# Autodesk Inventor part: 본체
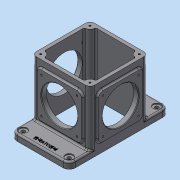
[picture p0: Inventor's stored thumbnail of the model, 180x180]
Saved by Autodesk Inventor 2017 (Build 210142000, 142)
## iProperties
Created: 2018-09
Part Number: 본체
Material: 알루미늄 6061
Document SubType Name: Modeling
Designer: mduedu
Density: 2.71 g/cm^3
Mass: 972.977 g
Surface Area: 957.184 cm^2
Volume: 359.032 cm^3
Appearance: 기본값
Author: mduedu
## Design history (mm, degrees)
sketch "스케치1"
  geometry: L1 (90, 52.5)-(-90, 52.5); L2 (-90, 52.5)-(-90, -52.5); L3 (-90, -52.5)-(90, -52.5); L4 (90, -52.5)-(90, 52.5); L5 (90, 52.5)-(-90, -52.5); L6 (-90, 52.5)-(90, -52.5); 1 further point
  constraints: 12 end point, 2 midpoint, 2 parallel, 1 horizontal, 1 perpendicular
  dimensions: "d0" = 180 distance of L3.end L2.end; "d1" = 105 distance of L2.end L1.end
extrude "돌출1" new body sketch "스케치1" distance "d2" = 12; taper "d3" = 0 deg
sketch "스케치2"
  geometry: L1 (-52.5, -52.5)-(52.5, -52.5); L2 (52.5, -52.5)-(52.5, 52.5); L3 (52.5, 52.5)-(-52.5, 52.5); L4 (-52.5, 52.5)-(-52.5, -52.5); L5 (-52.5, -52.5)-(52.5, 52.5); L6 (52.5, -52.5)-(-52.5, 52.5); 1 further point
  constraints: 12 end point, 2 midpoint, 2 parallel, 1 horizontal, 1 perpendicular
  dimensions: "d4" = 105 distance of L3.end L2.end; "d5" = 105 distance of L2.end L1.end
extrude "돌출2" join sketch "스케치2" distance "d6" = 100; taper "d7" = 0 deg
sketch "스케치14"
  geometry: L1 (-52.5, 52.5)-(52.5, 52.5) reference; L2 (52.5, 52.5)-(52.5, -52.5) reference; L3 (52.5, -52.5)-(-52.5, -52.5) reference; L4 (-52.5, -52.5)-(-52.5, 52.5) reference; L5 (46.5, 46.5)-(-46.5, 46.5); L6 (-46.5, 46.5)-(-46.5, -46.5); L7 (-46.5, -46.5)-(46.5, -46.5); L8 (46.5, -46.5)-(46.5, 46.5); 1 further point
  constraints: 8 end point, 3 other
  dimensions: "d85" = 6 distance between parallel lines of L5 L1
extrude "돌출10" cut sketch "스케치14" stored distance "d86" = 10; taper "d87" = 0 deg
fillet "모깎기1" dims "d12" = 8
sketch "스케치15"
  geometry: A1 r 8 centre (-44.5, 44.5) between (-44.5, 52.5) and (-52.5, 44.5) reference; A2 r 8 centre (44.5, 44.5) between (52.5, 44.5) and (44.5, 52.5) reference; A3 r 8 centre (44.5, -44.5) between (44.5, -52.5) and (52.5, -44.5) reference; A4 r 8 centre (-44.5, -44.5) between (-52.5, -44.5) and (-44.5, -52.5) reference; 5 further points
  constraints: 4 coincident, 4 vertical alignment, 8 other
extrude "돌출11" join sketch "스케치15" stored distance "d88" = 10; taper "d89" = 0 deg
fillet "모깎기15" dims "d90" = 3
sketch "스케치6"
  geometry: L1 (50, 19)-(130, 19); L2 (130, 19)-(130, 99); L3 (130, 99)-(50, 99); L4 (50, 99)-(50, 19); L5 (50, 19)-(130, 99); L6 (130, 19)-(50, 99); L7 (0, 0)-(180, 0) reference; 4 further points
  constraints: 12 end point, 4 midpoint, 2 parallel, 1 horizontal, 1 perpendicular, 1 vertical alignment
  dimensions: "d25" = 80 distance of L3.end L2.end; "d26" = 80 distance of L2.end L1.end; "d27" = 59 distance of point (90, 0) point (90, 59)
extrude "돌출6" join sketch "스케치6" distance "d28" = 3; taper "d29" = 0 deg
fillet "모깎기7" dims "d30" = 8
sketch "스케치7"
  geometry: C1 r 32.5 at (90, 59); 1 further point
  constraints: 1 centre point, 1 vertical alignment
  dimensions: "d32" = 65 diameter of C1; "d33" = 59 distance of C1.centre point (90, 0)
extrude "돌출7" cut sketch "스케치7" stored distance "d34" = 3; taper "d35" = 0 deg
fillet "모깎기9" dims "d36" = 3
sketch "스케치8"
  geometry: L1 (4.5, 7)-(84.5, 7); L2 (84.5, 7)-(84.5, 87); L3 (84.5, 87)-(4.5, 87); L4 (4.5, 87)-(4.5, 7); L5 (4.5, 7)-(84.5, 87); L6 (84.5, 7)-(4.5, 87); L7 (-8, -12)-(97, -12) reference; C1 r 32.5 at (44.5, 47); 4 further points
  constraints: 12 end point, 4 midpoint, 2 parallel, 1 centre point, 1 coincident, 1 horizontal, 1 perpendicular, 1 vertical alignment
  dimensions: "d37" = 80 distance of L3.end L2.end; "d38" = 80 distance of L2.end L1.end; "d39" = 59 distance from line of point (44.5, 47) L7; "d40" = 65 diameter of C1
extrude "돌출8" join sketch "스케치8" distance "d41" = 3; taper "d42" = 0 deg
fillet "모깎기10" dims "d43" = 8
extrude "돌출9" cut sketch "스케치8" stored distance "d44" = 3; taper "d45" = 0 deg
fillet "모깎기11" dims "d46" = 3
sketch "스케치9"
  geometry: L1 (50, 91)-(50, 27) reference; L2 (58, 19)-(122, 19) reference; L3 (130, 27)-(130, 91) reference; L4 (122, 99)-(58, 99) reference; C1 r 32.5 at (90, 59) reference; A1 r 8 centre (58, 91) between (58, 99) and (50, 91) reference; A2 r 8 centre (58, 27) between (50, 27) and (58, 19) reference; A3 r 8 centre (122, 27) between (122, 19) and (130, 27) reference; A4 r 8 centre (122, 91) between (130, 91) and (122, 99) reference; 5 further points
  constraints: 4 coincident
hole "구멍1" sketch "스케치9" at (58, 91), (122, 91), (122, 27), (58, 27) diameter "d47" = 3.242; stored, may be unused: countersink angle "d51" = 90 deg, drill point angle "d53" = 118 deg; dims "d48" = 6, "d49" = 4, "d50" = 2, "d52" = 9
sketch "스케치10"
  geometry: L1 (12.5, 7)-(76.5, 7) reference; L2 (84.5, 15)-(84.5, 79) reference; L3 (76.5, 87)-(12.5, 87) reference; L4 (4.5, 79)-(4.5, 15) reference; C1 r 32.5 at (44.5, 47) reference; A1 r 8 centre (12.5, 15) between (4.5, 15) and (12.5, 7) reference; A2 r 8 centre (76.5, 15) between (76.5, 7) and (84.5, 15) reference; A3 r 8 centre (76.5, 79) between (84.5, 79) and (76.5, 87) reference; A4 r 8 centre (12.5, 79) between (12.5, 87) and (4.5, 79) reference; 5 further points
  constraints: 4 coincident
hole "구멍2" sketch "스케치10" at (12.5, 79), (76.5, 79), (76.5, 15), (12.5, 15) diameter "d54" = 3.242; stored, may be unused: countersink angle "d58" = 90 deg, drill point angle "d60" = 118 deg; dims "d55" = 6, "d56" = 4, "d57" = 2, "d59" = 9
fillet "모깎기12" dims "d68" = 11
sketch "스케치16"
  geometry: A1 r 11 centre (-79, 41.5) between (-79, 52.5) and (-90, 41.5) reference; A2 r 11 centre (-79, -41.5) between (-90, -41.5) and (-79, -52.5) reference; A3 r 11 centre (79, 41.5) between (90, 41.5) and (79, 52.5) reference; A4 r 11 centre (79, -41.5) between (79, -52.5) and (90, -41.5) reference; 5 further points
  constraints: 4 coincident
hole "구멍5" sketch "스케치16" at (-79, 41.5), (79, 41.5), (79, -41.5), (-79, -41.5) diameter "d91" = 6.6; stored, may be unused: countersink angle "d95" = 90 deg, drill point angle "d97" = 118 deg; dims "d92" = 6, "d93" = 14, "d94" = 2, "d96" = 8
fillet "모깎기13" dims "d77" = 3
fillet "모깎기14" dims "d78" = 3
chamfer "모따기1" distance "d79" = 1; stored, may be unused: second distance "d80" = 2, angle "d81" = 45 deg
sketch "스케치17"
  geometry: A1 r 8 centre (-44.5, 44.5) between (-44.5, 52.5) and (-52.5, 44.5) reference; A2 r 8 centre (-44.5, -44.5) between (-52.5, -44.5) and (-44.5, -52.5) reference; A3 r 8 centre (44.5, -44.5) between (44.5, -52.5) and (52.5, -44.5) reference; A4 r 8 centre (44.5, 44.5) between (52.5, 44.5) and (44.5, 52.5) reference; 5 further points
  constraints: 4 coincident
hole "구멍6" sketch "스케치17" at (-44.5, 44.5), (44.5, 44.5), (44.5, -44.5), (-44.5, -44.5) diameter "d98" = 3.242; stored, may be unused: countersink angle "d102" = 90 deg, drill point angle "d104" = 118 deg; dims "d99" = 8, "d100" = 15, "d101" = 2, "d103" = 10
sketch "스케치13"
  geometry: L1 (90, -41.5)-(90, 41.5) reference; 2 further points
  constraints: 1 horizontal alignment, 1 other
  dimensions: "d82" = 10 distance from line of point (80, 0) L1
feature "엠보싱1" sketch "스케치13" dims "d0" = 180, "d1" = 105, "d25" = 80, "d26" = 80, "d27" = 59, "d83" = 0.5, "d84" = 0
node "솔리드1"
mirror "대칭1"
mirror "대칭2"
node "투영된 루프2"
node "투영된 루프3"
node "투영된 루프6"
